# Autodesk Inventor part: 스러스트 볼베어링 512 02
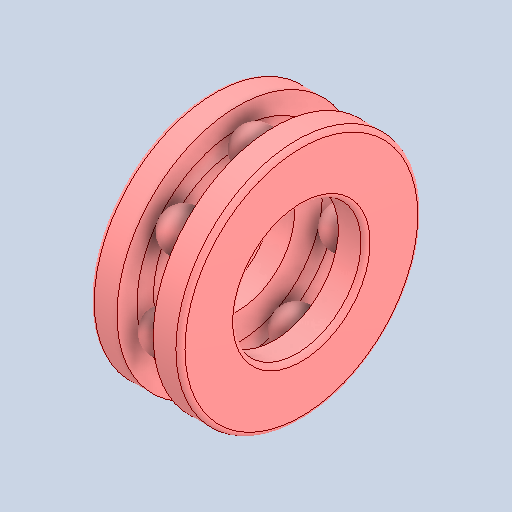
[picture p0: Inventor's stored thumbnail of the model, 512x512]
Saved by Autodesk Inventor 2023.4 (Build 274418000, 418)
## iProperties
Created: 2024-09
Part Number: 스러스트 볼베어링 512 02
Material: 강철, 연강
Description: 롤링 베어링 - 플랫 뒷면이 있는 스러스트 볼 베어링
Document SubType Name: Modeling
Designer: 11
Density: 7.85 g/cm^3
Appearance: 기본값
Author: jhkim
Sending System: Autodesk Inventor 2025
Preprocessor: ST-DEVELOPER v20
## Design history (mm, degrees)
node "스러스트 볼베어링 512 021"
node "솔리드1"
node "솔리드2"
node "솔리드3"
node "솔리드4"
node "솔리드5"
node "솔리드6"
node "솔리드7"
node "솔리드8"
node "솔리드9"
body "Solid1"
node "Solid1:1"
node "Solid1:2"
node "Solid1:3"
node "Solid1:4"
node "Solid1:5"
node "Solid1:6"
node "Solid1:7"
node "Solid1:8"
